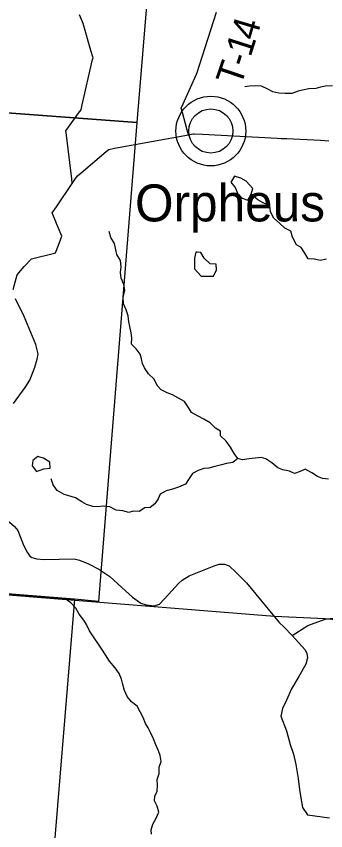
# Model space of a CAD drawing. Extents: x 0 to 42, y 0 to 22.
# Drawn here: x 7.704 to 8.033, y 16.803 to 17.672 of the extents above; entities that cross this region are included whole.
import ezdxf

# ---------------------------------------------------------------- set-up
doc = ezdxf.new("R2010")
doc.units = 0
for name, color, linetype in [('GM_X_County_Road', 7, 'Continuous'), ('GM_X_Minor_Lake', 7, 'Continuous'), ('GM_X_Minor_River', 7, 'Continuous'), ('GM_X_Section', 7, 'Continuous'), ('GM_X_Township', 7, 'Continuous'), ('GM_X_Township_Road', 7, 'Continuous'), ('GM_X_Township_Road_Text', 7, 'Continuous'), ('GM_X_Unincorporated', 7, 'Continuous'), ('GM_X_Unincorporated_Location', 7, 'Continuous'), ('GM_X_Unincorporated_Text', 7, 'Continuous')]:
    doc.layers.add(name, color=color, linetype=linetype)

msp = doc.modelspace()

# ---------------------------------------------------------------- linework, layer by layer
at = {"layer": 'GM_X_County_Road'}
for points in [[(7.70038, 17.38029), (7.70468, 17.39591), (7.7121, 17.4049), (7.71991, 17.4131), (7.74429, 17.41924), (7.74545, 17.41966), (7.74853, 17.42786), (7.75205, 17.43722), (7.74831, 17.44646), (7.74261, 17.46033), (7.74184, 17.46217), (7.74637, 17.46877), (7.76335, 17.49349), (7.76618, 17.49761), (7.76896, 17.50165), (7.77283, 17.50495), (7.79946, 17.52765), (7.80213, 17.52993), (7.80851, 17.5311), (7.88717, 17.54554), (7.89209, 17.54644), (7.89314, 17.54663), (7.90204, 17.54616), (7.98191, 17.54192), (7.98584, 17.5417), (7.99188, 17.54141), (8.02792, 17.53966)], [(8.02792, 17.53966), (8.03681, 17.53923)], [(7.70058, 17.25861), (7.71327, 17.2756), (7.71796, 17.28361), (7.72324, 17.29728), (7.72577, 17.30607), (7.72694, 17.31154), (7.7246, 17.32169), (7.7121, 17.35138), (7.70273, 17.37052)]]:
    msp.add_lwpolyline(points, dxfattribs=at)
at = {"layer": 'GM_X_Minor_Lake'}
for points in [[(7.95595, 17.48817), (7.94875, 17.49593), (7.94288, 17.49934), (7.93626, 17.50122), (7.93299, 17.49604)], [(7.93299, 17.49604), (7.9323, 17.49495), (7.93704, 17.48908), (7.9397, 17.48264), (7.94444, 17.47791), (7.95049, 17.47583), (7.95407, 17.4821), (7.95595, 17.48817)], [(7.89662, 17.42022), (7.89499, 17.42034), (7.89368, 17.4137), (7.8935, 17.40744), (7.89352, 17.40232), (7.9009, 17.39474)], [(7.9009, 17.39474), (7.91377, 17.39477), (7.91697, 17.40123), (7.91677, 17.4073), (7.91015, 17.40785), (7.90408, 17.41372), (7.90029, 17.41997), (7.89662, 17.42022)], [(7.72881, 17.20142), (7.7267, 17.20207), (7.72122, 17.1977), (7.72048, 17.19201), (7.72503, 17.18614)], [(7.72503, 17.18614), (7.73297, 17.18881), (7.73958, 17.18977), (7.73957, 17.19603), (7.73276, 17.20019), (7.72881, 17.20142)]]:
    msp.add_lwpolyline(points, dxfattribs=at)
at = {"layer": 'GM_X_Minor_River'}
for points in [[(8.04067, 17.5976), (8.0331, 17.59739), (8.028, 17.59624), (8.02308, 17.59509), (8.01552, 17.59451), (8.0089, 17.59298), (8.00399, 17.59202), (7.99737, 17.58973), (7.99037, 17.58953), (7.98338, 17.58989), (7.97713, 17.5914), (7.97164, 17.59404), (7.96521, 17.59725), (7.95877, 17.59762), (7.95216, 17.59741), (7.94724, 17.59664)], [(8.03439, 17.41285), (8.02759, 17.41132), (8.02153, 17.41263), (8.01491, 17.413), (8.01131, 17.41906), (8.00733, 17.42512), (8.0024, 17.42815), (7.99804, 17.4361), (7.99632, 17.44255), (7.99008, 17.44595), (7.9842, 17.45106), (7.97814, 17.45655), (7.97473, 17.46318), (7.97377, 17.46962), (7.96676, 17.47302), (7.96108, 17.47605), (7.95407, 17.4821)], [(8.03654, 17.17787), (8.0301, 17.17862), (8.02462, 17.18069), (8.01856, 17.18466), (8.01155, 17.18863), (8.00626, 17.18597), (8.0004, 17.18406), (7.99472, 17.18632), (7.98772, 17.18782), (7.98242, 17.1899), (7.97617, 17.1952), (7.96973, 17.19973), (7.96481, 17.20086), (7.95819, 17.20028), (7.95177, 17.19951), (7.94477, 17.19854), (7.93985, 17.20005), (7.93606, 17.20516), (7.93189, 17.21217), (7.92752, 17.21861), (7.92146, 17.22429), (7.92126, 17.22922), (7.91615, 17.23243), (7.91028, 17.23811), (7.90346, 17.24189), (7.8974, 17.24529), (7.8904, 17.24907), (7.88717, 17.25437), (7.88281, 17.26081), (7.87031, 17.26799), (7.86445, 17.27007), (7.8582, 17.27309), (7.85365, 17.27801), (7.85061, 17.28464), (7.84474, 17.29051), (7.84019, 17.29676), (7.83829, 17.30149), (7.83714, 17.30642), (7.83581, 17.31116), (7.83145, 17.31703), (7.82652, 17.32214), (7.82689, 17.32878), (7.82593, 17.33409), (7.8246, 17.34091), (7.82364, 17.34584), (7.82287, 17.3521), (7.82078, 17.35873), (7.81793, 17.36499), (7.81754, 17.37181), (7.81942, 17.37959), (7.81827, 17.38566), (7.81561, 17.39248), (7.81484, 17.39855), (7.8154, 17.40462), (7.81482, 17.41126), (7.81084, 17.41789), (7.80988, 17.42263), (7.80817, 17.42964), (7.80456, 17.4357), (7.80266, 17.44234)], [(7.93988, 17.20004), (7.93437, 17.19587), (7.92776, 17.19472), (7.92246, 17.19338), (7.91547, 17.19147), (7.90904, 17.18975), (7.90356, 17.18936), (7.89751, 17.18726), (7.89146, 17.18402), (7.88713, 17.17737), (7.88392, 17.17263), (7.87674, 17.16939), (7.87031, 17.1671), (7.86332, 17.16557), (7.85708, 17.16176), (7.85501, 17.15701), (7.85143, 17.15151), (7.84652, 17.1477), (7.84066, 17.14731), (7.8348, 17.14351), (7.82837, 17.14368), (7.82346, 17.14235), (7.81721, 17.14404), (7.81021, 17.14497), (7.8034, 17.14837), (7.7964, 17.14893), (7.79035, 17.14854), (7.78524, 17.14871), (7.77862, 17.15098), (7.77351, 17.15362), (7.76688, 17.15797), (7.75969, 17.16023), (7.75458, 17.16155), (7.74719, 17.1657), (7.74283, 17.17195), (7.74074, 17.1784)], [(7.80901, 16.97657), (7.80314, 16.98377), (7.79859, 16.99039), (7.79498, 16.99646), (7.79119, 17.00176), (7.78664, 17.00858), (7.78152, 17.01615), (7.77848, 17.02259), (7.77563, 17.02752), (7.7707, 17.03395), (7.7671, 17.0402), (7.76179, 17.04588), (7.75554, 17.05061)], [(7.84774, 16.79879), (7.84735, 16.80372), (7.84923, 16.80979), (7.85262, 16.81605), (7.85564, 16.82251), (7.85373, 16.82876), (7.85089, 16.83444), (7.85125, 16.83937), (7.85389, 16.84469), (7.85407, 16.85114), (7.85368, 16.85739), (7.85594, 16.86384), (7.85593, 16.87048), (7.85799, 16.87655), (7.85685, 16.883), (7.85532, 16.88792), (7.85229, 16.89437), (7.85001, 16.90081), (7.84678, 16.90763), (7.84431, 16.91236), (7.84146, 16.9171), (7.8388, 16.92354), (7.83577, 16.9296), (7.83235, 16.93566), (7.82648, 16.94039), (7.82174, 16.94607), (7.81889, 16.95232), (7.81718, 16.95877), (7.81584, 16.96445), (7.81318, 16.97051), (7.80901, 16.97657)]]:
    msp.add_lwpolyline(points, dxfattribs=at)
at = {"layer": 'GM_X_Section'}
for points in [[(7.36049, 18.10303), (7.87387, 18.06098), (7.83218, 17.55878), (7.32108, 17.59666)], [(7.32108, 17.59666), (7.83218, 17.55878), (7.79144, 17.04749), (7.76587, 17.04974), (7.2811, 17.08822)], [(7.23033, 17.09197), (7.2811, 17.08822), (7.76587, 17.04974), (7.72418, 16.54451), (7.19243, 16.58845)]]:
    msp.add_lwpolyline(points, close=True, dxfattribs=at)
at = {"layer": 'GM_X_Township'}
msp.add_lwpolyline([(8.42127, 18.51405), (8.38769, 18.10646), (8.32232, 17.47301), (8.30468, 17.09885), (8.29856, 17.02621), (8.2967, 17.00562), (8.09356, 17.02392), (8.06488, 17.0255), (8.03278, 17.02883), (7.97896, 17.0312), (7.36254, 17.08083), (7.35717, 17.08127), (7.35122, 17.08175), (7.35051, 17.0818), (7.34212, 17.08248), (7.2769, 17.08773), (7.22466, 17.09014), (6.78886, 17.12464), (6.70312, 17.1317), (6.64854, 17.1358), (6.05163, 17.18401)], dxfattribs=at)
at = {"layer": 'GM_X_Township_Road'}
for points in [[(7.88717, 17.54554), (7.88588, 17.55032), (7.88071, 17.56943), (7.87948, 17.57397), (7.88159, 17.57871), (7.89567, 17.61038), (7.89636, 17.61193), (7.89886, 17.61973), (7.91697, 17.67631)], [(7.76335, 17.49349), (7.76274, 17.49843), (7.75666, 17.54791), (7.75644, 17.54967), (7.76123, 17.55631), (7.76999, 17.56844), (7.77275, 17.57226), (7.77392, 17.57738), (7.78506, 17.62596), (7.78545, 17.62768), (7.78315, 17.63555), (7.77477, 17.66427), (7.77426, 17.66602), (7.77091, 17.67344)], [(8.17227, 15.49063), (8.24231, 16.32059), (8.26133, 16.54947), (8.2967, 17.00562), (8.09356, 17.02392), (8.06488, 17.0255), (8.03278, 17.02883), (7.97896, 17.0312), (7.36254, 17.08083), (7.35717, 17.08127), (7.35122, 17.08175), (7.35051, 17.0818), (7.34212, 17.08248), (7.2769, 17.08773), (7.22466, 17.09014), (6.78886, 17.12464), (6.70312, 17.1317), (6.64854, 17.1358), (6.05163, 17.18401)], [(7.68932, 17.13825), (7.69644, 17.13209), (7.70188, 17.12722), (7.70517, 17.12293), (7.70789, 17.11677), (7.71147, 17.10761), (7.71533, 17.09988), (7.71819, 17.09588), (7.71991, 17.09462)], [(7.71991, 17.09462), (7.72034, 17.0943), (7.72521, 17.09273), (7.73351, 17.09201), (7.76528, 17.09273), (7.77101, 17.09144), (7.7806, 17.08757), (7.79176, 17.08185), (7.80336, 17.07398), (7.8161, 17.0621), (7.8274, 17.05208), (7.83642, 17.04549), (7.84204, 17.04365), (7.85045, 17.04263), (7.85617, 17.04463), (7.86605, 17.05465), (7.87664, 17.06668), (7.88051, 17.07011), (7.88809, 17.07484), (7.91457, 17.08543), (7.91987, 17.08715), (7.92559, 17.08729), (7.93046, 17.08543), (7.93819, 17.07842), (7.94921, 17.06725), (7.97907, 17.03094), (7.98433, 17.0246), (7.98871, 17.02027), (7.99785, 17.01097)], [(7.99785, 17.01097), (8.01445, 17.02171), (8.03288, 17.02857), (8.03831, 17.02931), (8.04473, 17.02952), (8.06632, 17.02731), (8.09367, 17.02366), (8.10496, 17.02371)], [(7.99785, 17.01097), (8.01163, 16.99566), (8.01348, 16.99176), (8.01424, 16.9872), (8.01218, 16.98036), (8.0048, 16.96723), (7.99719, 16.95417), (7.99165, 16.94204), (7.98727, 16.93314), (7.98553, 16.92498), (7.99154, 16.90921), (7.99547, 16.89458), (7.99922, 16.88432), (8.00164, 16.87331), (8.00405, 16.8585), (8.00552, 16.84654), (8.00719, 16.83553), (8.00887, 16.82755), (8.01395, 16.81956), (8.03761, 16.81645)]]:
    msp.add_lwpolyline(points, dxfattribs=at)
at = {"layer": 'GM_X_Unincorporated'}
for radius in [0.0372, 0.02358]:
    msp.add_circle((7.91103, 17.54954), radius, dxfattribs=at)
at = {"layer": 'GM_X_Unincorporated_Location'}
msp.add_line((7.91103, 17.54954), (7.91103, 17.54954), dxfattribs=at)

# ---------------------------------------------------------------- texts
at = {"layer": 'GM_X_Township_Road_Text'}
for s, rotation, p in [('4', 73.4903, (7.9589, 17.64503)), ('1', 72.1471, (7.95332, 17.62767)), ('-', 72.08454, (7.94972, 17.61654)), ('T', 71.17473, (7.94271, 17.59596))]:
    msp.add_text(s, height=0.02841, rotation=rotation, dxfattribs=at).set_placement(p)
at = {"layer": 'GM_X_Unincorporated_Text'}
msp.add_text('Orpheus', height=0.039489, rotation=0.00001, dxfattribs=at).set_placement((7.83022, 17.45304))

doc.saveas('drawing.dxf')
